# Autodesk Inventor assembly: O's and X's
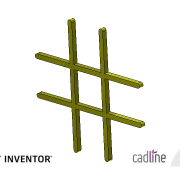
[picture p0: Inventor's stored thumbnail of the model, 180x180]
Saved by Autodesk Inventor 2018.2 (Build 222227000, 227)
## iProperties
Created: 2018-03
Part Number: O's and X's
Document SubType Name: Assembly
Designer: PeterMaxwell-Stewart
Mass: 12.8927 g
Surface Area: 102.712 cm^2
Volume: 12.8927 cm^3
Density: 1 g/cm^3
RuleStatus: InUse
AfterDocOpen0: Show Form
COBieSize: 0.0
Author: PeterMaxwell-Stewart
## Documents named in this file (28)
- C:\Users\PeterMaxwell-Stewart\OneDrive - CADline Limited\Inventor\Cadline\O's and X's\O's and X's.iam
- C:\Users\PeterMaxwell-Stewart\OneDrive - CADline Limited\Inventor\Cadline\O's and X's\Mid Centre O.ipt
- C:\Users\PeterMaxwell-Stewart\OneDrive - CADline Limited\Inventor\Cadline\O's and X's\Mid Centre X.ipt
- C:\Users\PeterMaxwell-Stewart\OneDrive - CADline Limited\Inventor\Cadline\O's and X's\Top Centre X.ipt
- C:\Users\PeterMaxwell-Stewart\OneDrive - CADline Limited\Inventor\Cadline\O's and X's\Top centre O.ipt
- C:\Users\PeterMaxwell-Stewart\OneDrive - CADline Limited\Inventor\Cadline\O's and X's\Bottom Centre X.ipt
- C:\Users\PeterMaxwell-Stewart\OneDrive - CADline Limited\Inventor\Cadline\O's and X's\Bottom Centre O.ipt
- C:\Users\PeterMaxwell-Stewart\OneDrive - CADline Limited\Inventor\Cadline\O's and X's\Mid Right X.ipt
- C:\Users\PeterMaxwell-Stewart\OneDrive - CADline Limited\Inventor\Cadline\O's and X's\Mid Right O.ipt
- C:\Users\PeterMaxwell-Stewart\OneDrive - CADline Limited\Inventor\Cadline\O's and X's\Top Right X.ipt
- C:\Users\PeterMaxwell-Stewart\OneDrive - CADline Limited\Inventor\Cadline\O's and X's\Top Right O.ipt
- C:\Users\PeterMaxwell-Stewart\OneDrive - CADline Limited\Inventor\Cadline\O's and X's\Bottom Right X.ipt
- C:\Users\PeterMaxwell-Stewart\OneDrive - CADline Limited\Inventor\Cadline\O's and X's\Bottom Right O.ipt
- C:\Users\PeterMaxwell-Stewart\OneDrive - CADline Limited\Inventor\Cadline\O's and X's\Mid Left X.ipt
- C:\Users\PeterMaxwell-Stewart\OneDrive - CADline Limited\Inventor\Cadline\O's and X's\Mid Left O.ipt
- C:\Users\PeterMaxwell-Stewart\OneDrive - CADline Limited\Inventor\Cadline\O's and X's\Top Left X.ipt
- C:\Users\PeterMaxwell-Stewart\OneDrive - CADline Limited\Inventor\Cadline\O's and X's\Top Left O.ipt
- C:\Users\PeterMaxwell-Stewart\OneDrive - CADline Limited\Inventor\Cadline\O's and X's\Bottom Left X.ipt
- C:\Users\PeterMaxwell-Stewart\OneDrive - CADline Limited\Inventor\Cadline\O's and X's\Bottom Left O.ipt
- C:\Users\PeterMaxwell-Stewart\OneDrive - CADline Limited\Inventor\Cadline\O's and X's\Frame.ipt
- C:\Users\PeterMaxwell-Stewart\OneDrive - CADline Limited\Inventor\Cadline\O's and X's\Central Win.ipt
- C:\Users\PeterMaxwell-Stewart\OneDrive - CADline Limited\Inventor\Cadline\O's and X's\Mid Win.ipt
- C:\Users\PeterMaxwell-Stewart\OneDrive - CADline Limited\Inventor\Cadline\O's and X's\Diagonal Up Win.ipt
- C:\Users\PeterMaxwell-Stewart\OneDrive - CADline Limited\Inventor\Cadline\O's and X's\Top Win.ipt
- C:\Users\PeterMaxwell-Stewart\OneDrive - CADline Limited\Inventor\Cadline\O's and X's\Bottom Win.ipt
- C:\Users\PeterMaxwell-Stewart\OneDrive - CADline Limited\Inventor\Cadline\O's and X's\Right Win.ipt
- C:\Users\PeterMaxwell-Stewart\OneDrive - CADline Limited\Inventor\Cadline\O's and X's\Left Win.ipt
- C:\Users\PeterMaxwell-Stewart\OneDrive - CADline Limited\Inventor\Cadline\O's and X's\Diagonal Down Win.ipt
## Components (27 placed, 27 different names)
1. Mid Centre O:1
2. Mid Centre X:1
3. Top Centre X:1
4. Top centre O:1
5. Bottom Centre X:1
6. Bottom Centre O:1
7. Mid Right X:1
8. Mid Right O:1
9. Top Right X:1
10. Top Right O:1
11. Bottom Right X:1
12. Bottom Right O:1
13. Mid Left X:1
14. Mid Left O:1
15. Top Left X:1
16. Top Left O:1
17. Bottom Left X:1
18. Bottom Left O:1
19. Frame:1
20. Central Win:1
21. Mid Win:1
22. Diagonal Up Win:1
23. Top Win:1
24. Bottom Win:1
25. Right Win:1
26. Left Win:1
27. Diagonal Down Win:1
